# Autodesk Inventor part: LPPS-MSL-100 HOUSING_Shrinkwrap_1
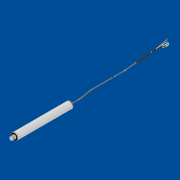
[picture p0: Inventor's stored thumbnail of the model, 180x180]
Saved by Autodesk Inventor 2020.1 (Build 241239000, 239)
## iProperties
Created: 2019-07
Part Number: LPPS-MSL-100 HOUSING_Shrinkwrap_1
Material: Generic
Document SubType Name: Modeling
Designer: J. Nielson
Density: 1 g/cm^3
Appearance: Default
Author: J. Nielson
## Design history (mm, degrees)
node "Assembly1"
body "Solid1"
node "Part1:1"
node "Part2:1"
body "Solid2"
node "Part3:1"
body "Solid3"
node "Part4:1"
body "Solid4"
node "Part5:1"
body "Solid5"
node "Part6:1"
body "Solid6"
node "Part7:1"
body "Solid7"
node "Part8:1"
body "Solid8"
node "Part9:1"
body "Solid9"
node "Part10:1"
body "Solid10"
node "Part11:1"
body "Solid11"
node "Part12:1"
body "Solid12"
node "Part13:1"
body "Solid13"
node "Part14:1"
body "Solid14"
node "Part15:1"
body "Solid15"
node "Part16:1"
body "Solid16"
node "Part17:1"
body "Solid17"
node "Part16:2"
body "Solid18"
node "Part17:2"
body "Solid19"
